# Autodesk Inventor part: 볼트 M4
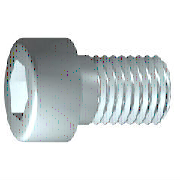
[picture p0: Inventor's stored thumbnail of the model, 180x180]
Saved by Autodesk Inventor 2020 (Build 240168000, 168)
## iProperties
Created: 2012-02
Part Number: 볼트 M4
Material: 강철, 연강
Description: 6각머리 태핑 나사
Document SubType Name: Modeling
Standard: KS B 1003
Designer: mduedu
Standards Organization: KS
Language: ko-KR
Size Designation: M 4 x 10
Categories: <MemberInstance><Categories><Category DisplayName="조임쇠" InternalName="e4da775c-781d-43d5-af7c-5136215cf5a6" Mnemonic="FSTN"><Category DisplayName="볼트" InternalN
Density: 7.86 g/cm^3
Mass: 2.0371 g
Surface Area: 3.0572 cm^2
Volume: 0.259174 cm^3
Appearance: 강철
IsCustomPart: 1
Author: mduedu
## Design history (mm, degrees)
sketch "스케치1"
  geometry: L1 (-1, 0)-(10, 0); L2 (10, 0)-(10, 2); L3 (10, 2)-(1.75, 2); L4 (1.75, 2)-(1.32, 2); L5 (1.32, 2)-(0, 2); L6 (0, 2)-(0, 3.5); L7 (0, 3.5)-(-4, 3.5); L8 (-4, 3.5)-(-4, 1.732); L9 (-4, 1.732)-(-2, 1.732); L10 (-2, 1.732)-(-1, 0); L11 (-6.8, 0)-(12.8, 0) reference; L12 (0, -0.7)-(0, 4.2) reference; L13 (1.75, 2)-(0, 2)
  constraints: 22 end point, 6 parallel, 2 collinear, 2 perpendicular, 1 horizontal, 1 point on line
  dimensions: "d1" = 8.25 distance from line of L3.end L2 (= GEL); "d2" = 0.42952 distance of L4.end L3.end (computed from GAL); "d3" = 4 distance between parallel lines of L8 L6 (= KOH); "d4" = 2 distance of L8.end L9.end (= INTI); "d5" = 60 deg angle of L10 L1; "d6" = 4 diameter of L3 L1 (= GD); "d7" = 4 diameter of L5 L1 (= BDM); "d8" = 3.4641 diameter of L9 L1 (= 1.1547 x SW); "d9" = 7 diameter of L7 L1 (= KOD); "d26" = 10 distance between parallel lines of L12 L2 (= NLG)
revolve "본체" sketch "스케치1" stored, may be unused: angle "d10" = 90 deg
sketch "스케치2"
  geometry: L1 (0, -4.9)-(0, 4.9) reference; L2 (-4.9, 0)-(4.9, 0) reference; L3 (1.732, 0)-(0.866, -1.5); L4 (0.866, -1.5)-(-0.866, -1.5); L5 (-0.866, -1.5)-(-1.732, 0); L6 (-1.732, 0)-(-0.866, 1.5); L7 (-0.866, 1.5)-(0.866, 1.5); L8 (0.866, 1.5)-(1.732, 0); 2 further points
  constraints: 12 end point, 1 coincident, 1 horizontal alignment, 1 point on line, 12 other
extrude "슬롯" join sketch "스케치2" stored distance "d11" = 10; taper "d12" = 0 deg
workplane "Work Plane1"
fillet "Fillet2" dims "d30" = 0.1 (= R)
body "Solid1"
fillet "모깎기1" dims "d17" = 0.4 (= RR)
feature "스레드" dims "d13" = 8.25 (= GEL), "d14" = 0
chamfer "모따기1" distance "d15" = 0.42941 (= -0.5 x SPD + 0.5 x GD); stored, may be unused: second distance "d16" = 0.42941 (= GUL), angle "d27" = 45 deg
other parameters: "GD" = 4 (= NND) [user parameter; used in 2 equation terms], "NLG" = 10 [user parameter; used in 1 equation term], "GEL" = 8.25 [user parameter; used in 2 equation terms], "KOD" = 7 [user parameter; used in 1 equation term], "KOH" = 4 [user parameter; used in 1 equation term], "INTI" = 2 [user parameter; used in 1 equation term], "GAL" = 0.42941 (= 0.61345 x PTC) [user parameter; used in 1 equation term], "GUL" = 0.42941 (= 0.61345 x PTC) [user parameter; used in 1 equation term], "BDM" = 4 (= NND) [user parameter; used in 1 equation term], "SW" = 3 [user parameter; used in 2 equation terms], "RR" = 0.4 [user parameter; used in 1 equation term], "SPD" = 3.14117 (= NND - 1.2269 x PTC) [user parameter; used in 1 equation term], "d19" = 0, "d28" = 0, "d29" = 0, "R" = 0.1 [user parameter; used in 1 equation term], "PHH" = 0.2 [user parameter], "GD1" = 3.14117 (= THREADDIA - 1.2269 x PTC) [user parameter], "THREADDIA" = 4 [user parameter; used in 1 equation term], "FAWI" = 45 deg [user parameter], "TPU" = 14.28571 (computed from PTC) [user parameter], "PTC" = 0.7 [user parameter; used in 5 equation terms], "NND" = 4 [user parameter; used in 3 equation terms], "TOA" = 30 deg [user parameter], "E0" = 3.465 (= 1.155 x SW) [user parameter]
